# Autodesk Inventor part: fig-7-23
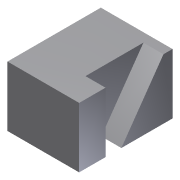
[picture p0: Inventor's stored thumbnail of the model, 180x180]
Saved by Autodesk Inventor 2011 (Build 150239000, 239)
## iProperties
Created: 2010-03
Part Number: fig-7-23
Document SubType Name: Modeling
Designer: CADSoft
Density: 1 g/cm^3
Author: CADSoft
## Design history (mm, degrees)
sketch "Sketch1"
  geometry: L1 (-16.027, 20.205)-(19.726, 20.205); L2 (19.726, 20.205)-(19.726, -26.37); L3 (19.726, -26.37)-(-16.027, -26.37); L4 (-16.027, -26.37)-(-16.027, 20.205); 1 further point
  constraints: 8 end point, 2 parallel, 1 horizontal, 1 perpendicular
extrude "Extrusion1" new body sketch "Sketch1" distance "d0" = 30; taper "d1" = 0 deg
sketch "Sketch2"
  geometry: L1 (-30, 46.575)-(-30, 0) reference; L2 (0, 46.575)-(0, 0) reference; L3 (-30, 13.159)-(0, 13.159); L4 (0, 13.159)-(0, 33.527); L5 (0, 33.527)-(-30, 33.527); L6 (-30, 33.527)-(-30, 13.159); 1 further point
  constraints: 8 end point, 2 parallel, 2 point on line, 1 horizontal, 1 perpendicular
extrude "Extrusion2" cut sketch "Sketch2" distance "d2" = 10; taper "d3" = 0 deg
feature "Move Face1"
feature "Move Face2"
body "Solid1"
